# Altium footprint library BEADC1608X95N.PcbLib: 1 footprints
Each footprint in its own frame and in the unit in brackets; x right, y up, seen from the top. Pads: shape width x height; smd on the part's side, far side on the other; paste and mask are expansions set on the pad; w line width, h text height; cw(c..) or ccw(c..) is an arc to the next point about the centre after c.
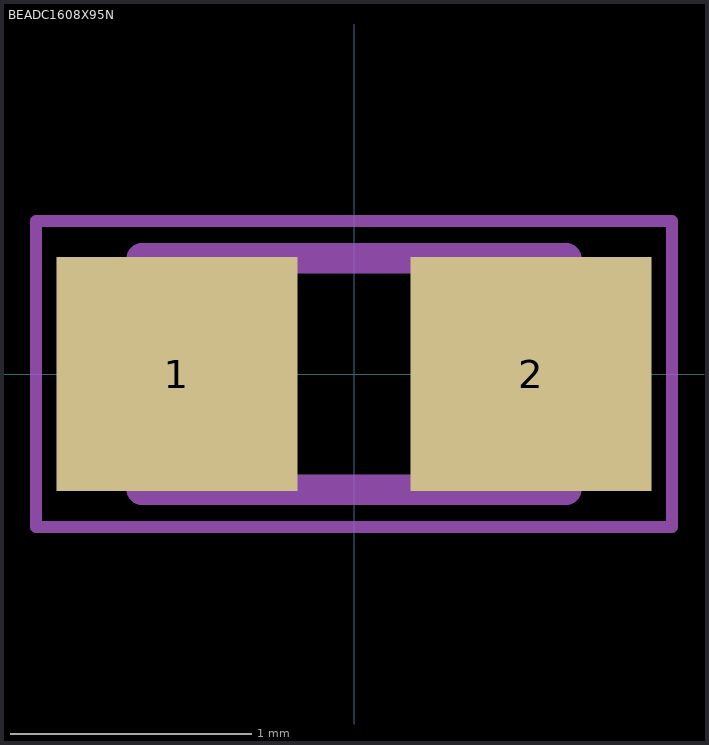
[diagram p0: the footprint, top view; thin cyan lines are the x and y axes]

## BEADC1608X95N [mm]
pads (2):
  rect 1x0.97 smd: 1(-0.735,0) 2(0.735,0)
Mechanical 13:
  lines w0.127: -0.88,-0.48 0.88,-0.48 0.88,0.48 -0.88,0.48 -0.88,-0.48
Mechanical 15:
  lines w0.05: -1.321,-0.635 1.321,-0.635 1.321,0.635 -1.321,0.635 -1.321,-0.635
3D body "step_temp.STEP": height 0.95, standoff 0, extent -0.8,-0.4 0.8,0.4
